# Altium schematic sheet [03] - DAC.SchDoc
size A4; DocumentNumber: 3; SheetNumber: 3; SheetTotal: 5
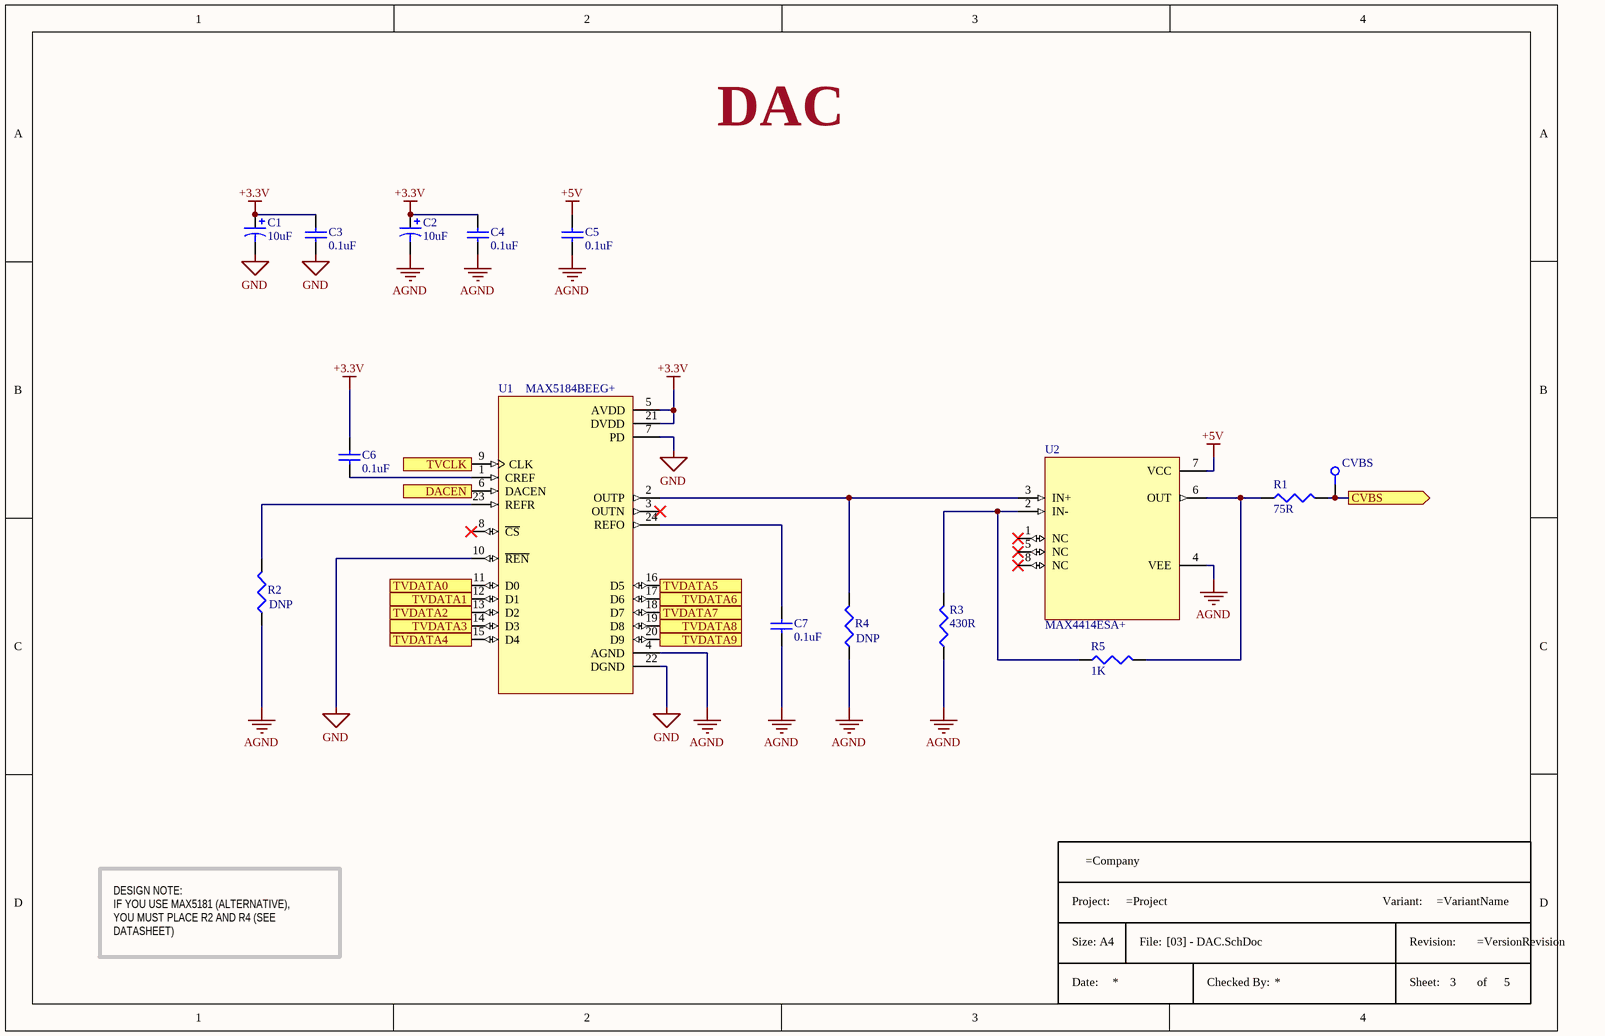
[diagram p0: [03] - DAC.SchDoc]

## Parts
*  Title Block A4  (value not drawn)  (graphical)
C1  10uF  [C1206T]
C2  10uF  [C1206T]
C3  0.1uF  [C1206]
C4  0.1uF  [C1206]
C5  0.1uF  [C1206]
C6  0.1uF  [C1206]
C7  0.1uF  [C1206]
CVBS  TP_25MILC  [TP_25C]  (value not drawn)  (no BOM)
R1  75R  [R0603]
R2  DNP  [R0603]
R3  430R  [R0603]
R4  DNP  [R0603]
R5  1K  [R0603]
U1  MAX5184BEEG+  [SOP63P602X175-24N]
U2  MAX4414ESA+  [SOIC127P600X175-8N]

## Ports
CVBS (out), DACEN (in), TVCLK (in), TVDATA0 (in), TVDATA1 (in), TVDATA2 (in), TVDATA3 (in), TVDATA4 (in), TVDATA5 (in), TVDATA6 (in), TVDATA7 (in), TVDATA8 (in), TVDATA9 (in)

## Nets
+3.3V: C1.1 C2.1 C3.2 C4.2 C6.1 U1.5(AVDD) U1.21(DVDD)
+5V: C5.2 U2.7(VCC)
AGND: C2.2 C4.1 C5.1 C7.1 R2.1 R3.1 R4.1 U1.4(AGND) U2.4(VEE)
GND: C1.2 C3.1 U1.7(PD) U1.10(~{REN}) U1.22(DGND)
CVBS: CVBS.1 R1.2 ; port CVBS
DACEN: U1.6(DACEN) ; port DACEN
TVCLK: U1.9(CLK) ; port TVCLK
TVDATA0: U1.11(D0) ; port TVDATA0
TVDATA1: U1.12(D1) ; port TVDATA1
TVDATA2: U1.13(D2) ; port TVDATA2
TVDATA3: U1.14(D3) ; port TVDATA3
TVDATA4: U1.15(D4) ; port TVDATA4
TVDATA5: U1.16(D5) ; port TVDATA5
TVDATA6: U1.17(D6) ; port TVDATA6
TVDATA7: U1.18(D7) ; port TVDATA7
TVDATA8: U1.19(D8) ; port TVDATA8
TVDATA9: U1.20(D9) ; port TVDATA9
NetC6_2: C6.2 U1.1(CREF)
NetC7_2: C7.2 U1.24(REFO)
NetR1_1: R1.1 R5.2 U2.6(OUT)
NetR2_2: R2.2 U1.23(REFR)
NetR3_2: R3.2 R5.1 U2.2(IN-)
NetR4_2: R4.2 U1.2(OUTP) U2.3(IN+)

Not connected (* = marked no-connect by the designer): U1 3(OUTN)* 8(~{CS})*; U2 1(NC)* 5(NC)* 8(NC)*

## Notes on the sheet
- DAC
- DESIGN NOTE:
  IF YOU USE MAX5181 (ALTERNATIVE), YOU MUST PLACE R2 AND R4 (SEE DATASHEET)

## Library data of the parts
C1 C2 = T491A106K010AT: CAPACITOR, CASE A, 10UF, 10V; Product Range:KEMET - T491 Series; Capacitance:10µF; Capacitance Tolerance:± 10%; Voltage Rating:10V; Capacitor Case Style:1206 [3216 Metric]; Manufacturer Size Code:A; Operating Temperature Max:125°C; ;RoHS Compliant: Yes; Manufacturer: KEMET; Dielectric Material: Tantalum; ESR (Equivalent Series Resistance): 4R; Life (Hours): 2000Hour; Polarity: Polar; Dissipation Factor: 6%; Leakage Current: 1uA; Ripple Current: 137mA
C3-C7 = GRM319R71H104KA01D: MURATA - GRM319R71H104KA01D - COND, CERÁ MULT, X7R, 100NF, 50V, 1206
CVBS = TP_25MILC: Test Point 25mil
R1 = CRCW060375R0FKEA: VISHAY - CRCW060375R0FKEA - RES, 75R, 1%, 0.1W, 0603, THICK FILM; Power Rating: 100mW; Temperature Coefficient: 100ppm/°C; Voltage Rating: 75V
R2 R4 = R0603
R3 = MCWF06R4300BTL: Res, 430R, 0.1%, 0.1W, 0603, Thin Film; Manufacturer: Multicomp; Voltage Rating (DC): 75V; Temperature Coefficient: 25ppm/°C; Power Rating: 100mW
R5 = ESR03EZPF1001: ROHM - ESR03EZPF1001 - SMD Chip Resistor, Anti-Surge, 0603 [1608 Metric], 1 kohm, ESR Series, 150 V, Thick Film, 250 mW; Temperature Coefficient: 100ppm/°C; Max Power Dissipation: 250mW; Resistance: 1kR; Tolerance: 1%
U1 = MAX5184BEEG+: DAC 1-CH Current Steering 10-bit 24-Pin QSOP; Manufacturer: Maxim; Integral Nonlinearity (INL): 2LSB; Full Scale Error: 40LSB; Resolution: 10b; Output Type: Voltage; Interface: Parallel; Supply Type: Analog,Digital; Number of Converters: 1; Settling Time: 25us; Number of Bits: 10; Max Supply Voltage: 3.3V; Min Supply Voltage: 2.7V
U2 = MAX4414ESA+: IC OPAMP VFB 400MHZ RRO 8SOIC; Manufacturer: Maxim; Min Supply Voltage: 2.7V; Max Supply Voltage: 5.5V; Voltage Gain: 80dB; Common Mode Rejection Ratio: 65dB; Slew Rate: 200V/µs; Input Offset Voltage (Vos): 500uV; Operating Supply Current: 1.6mA; Number of Channels: 1; Output Current per Channel: 75mA; Input Bias Current: 1.3uA; Max Power Dissipation: 471mW; Power Supply Rejection Ratio (PSRR): 77dB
